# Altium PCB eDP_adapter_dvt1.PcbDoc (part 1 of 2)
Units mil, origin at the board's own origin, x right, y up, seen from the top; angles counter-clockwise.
Board outline 1964.57 x 1377.95 mil, 4 copper layers (Top Layer, Internal Plane 1, Internal Plane 2, Bottom Layer), stack 65.8 mil thick; 112 components, 78 nets, 1150 pads, 214 vias.
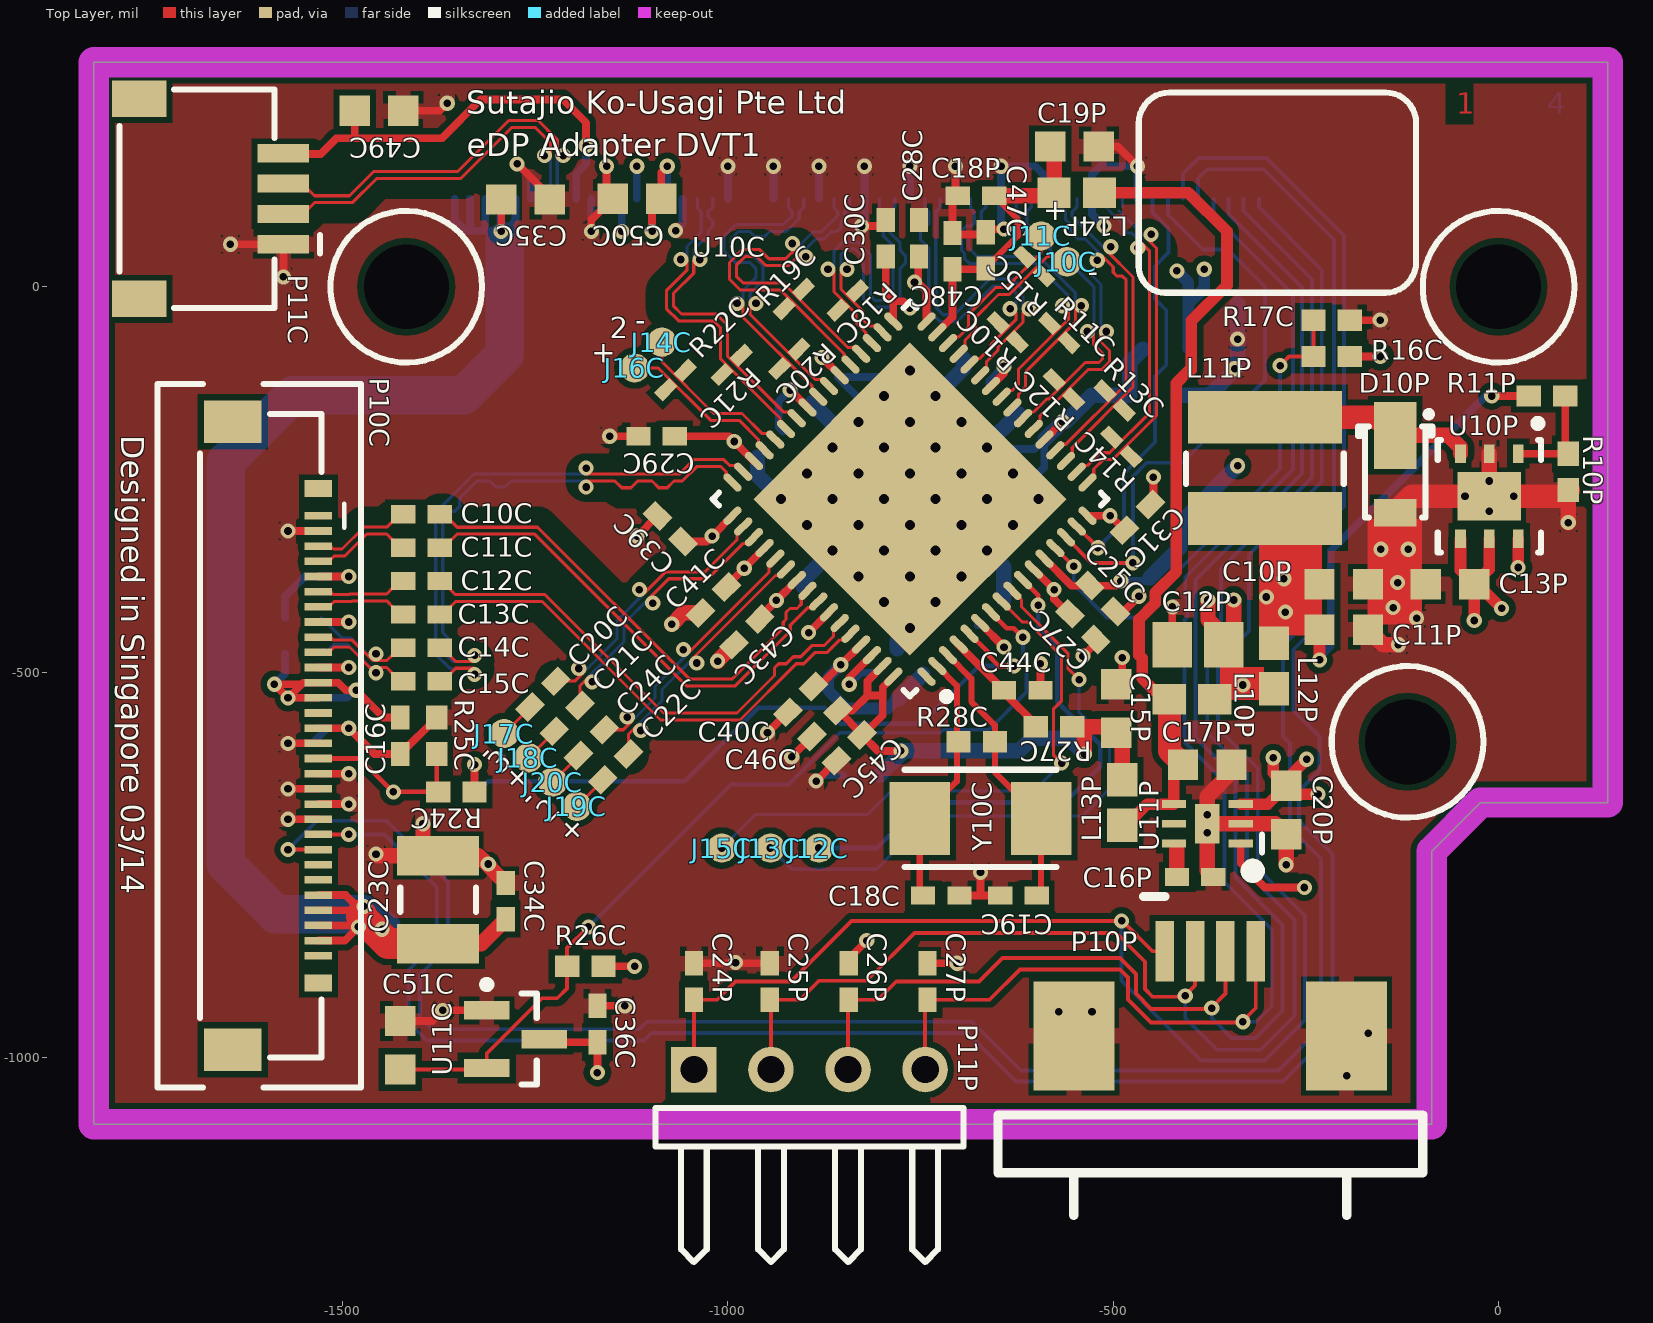
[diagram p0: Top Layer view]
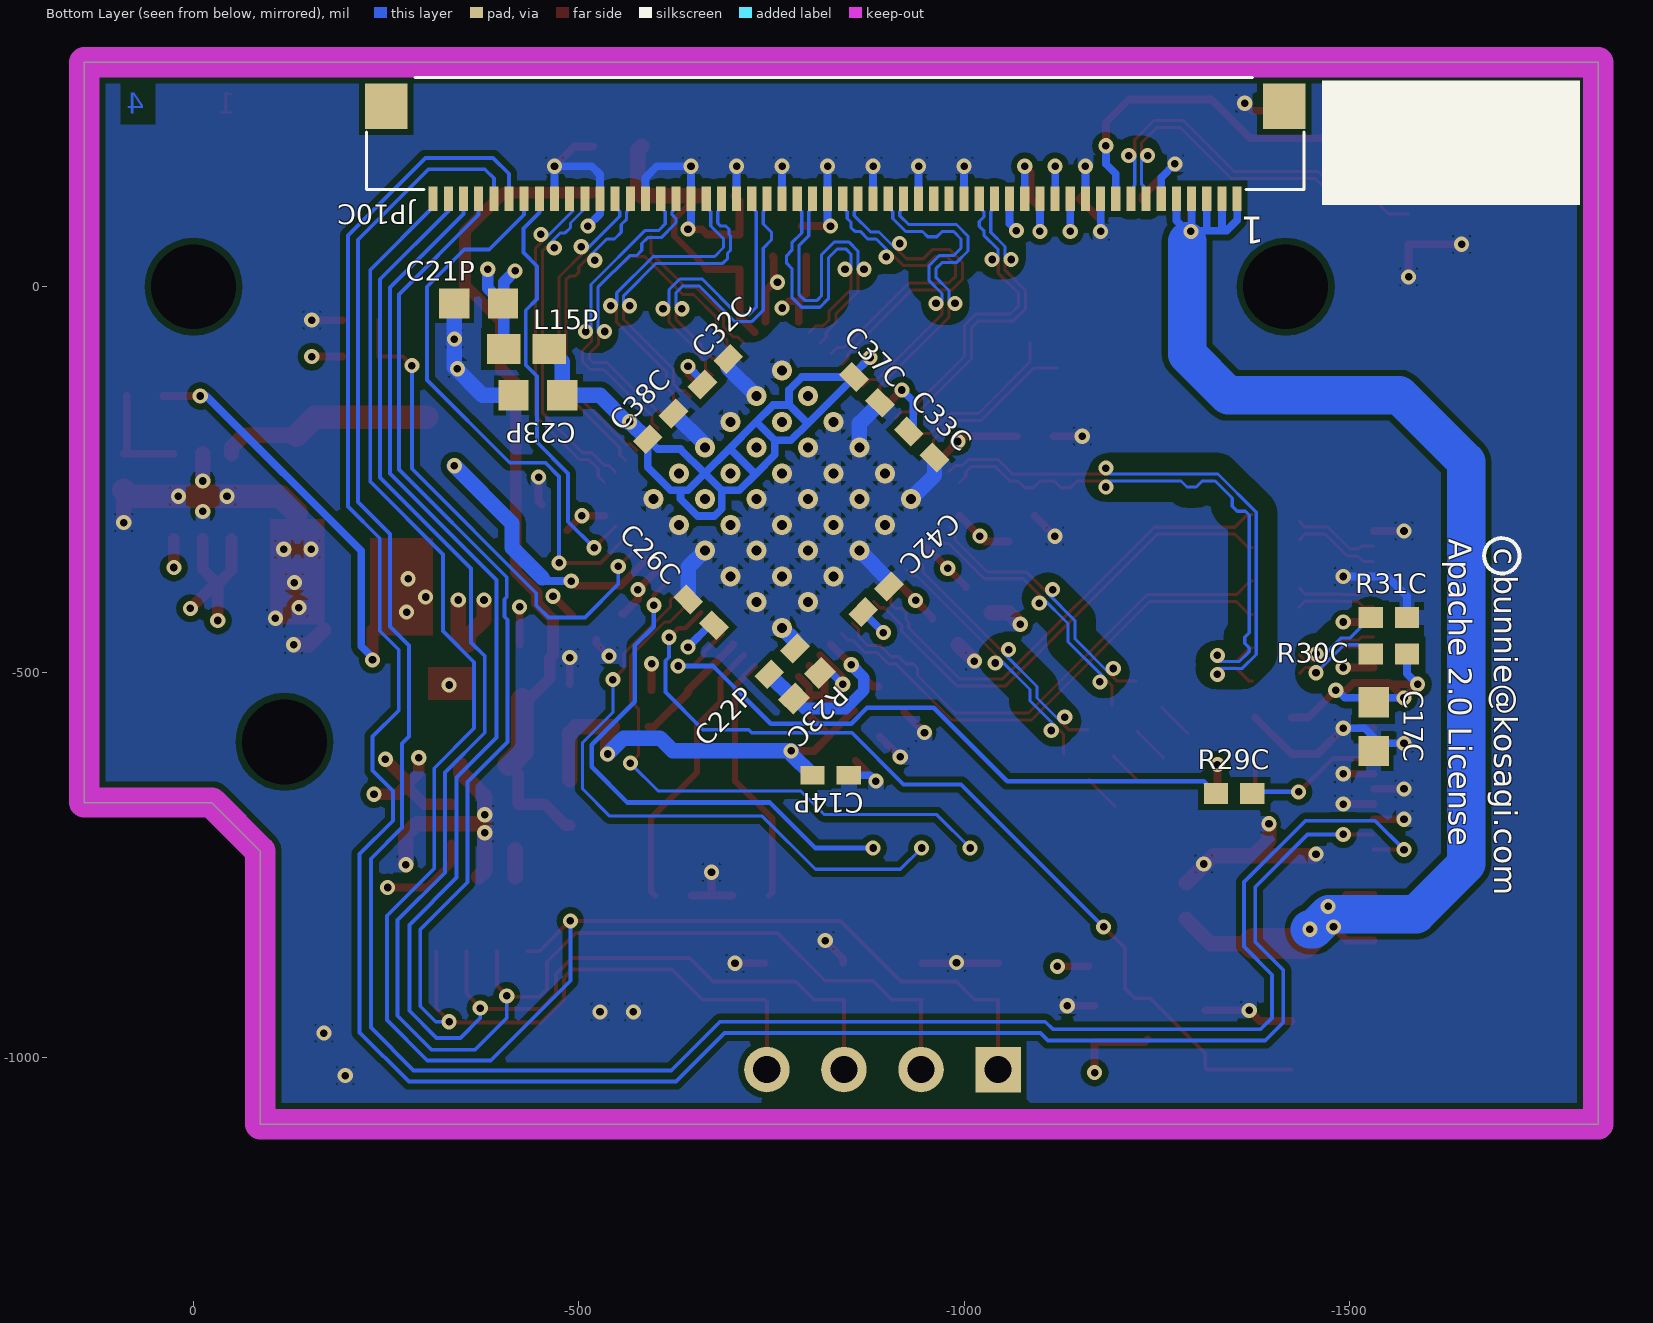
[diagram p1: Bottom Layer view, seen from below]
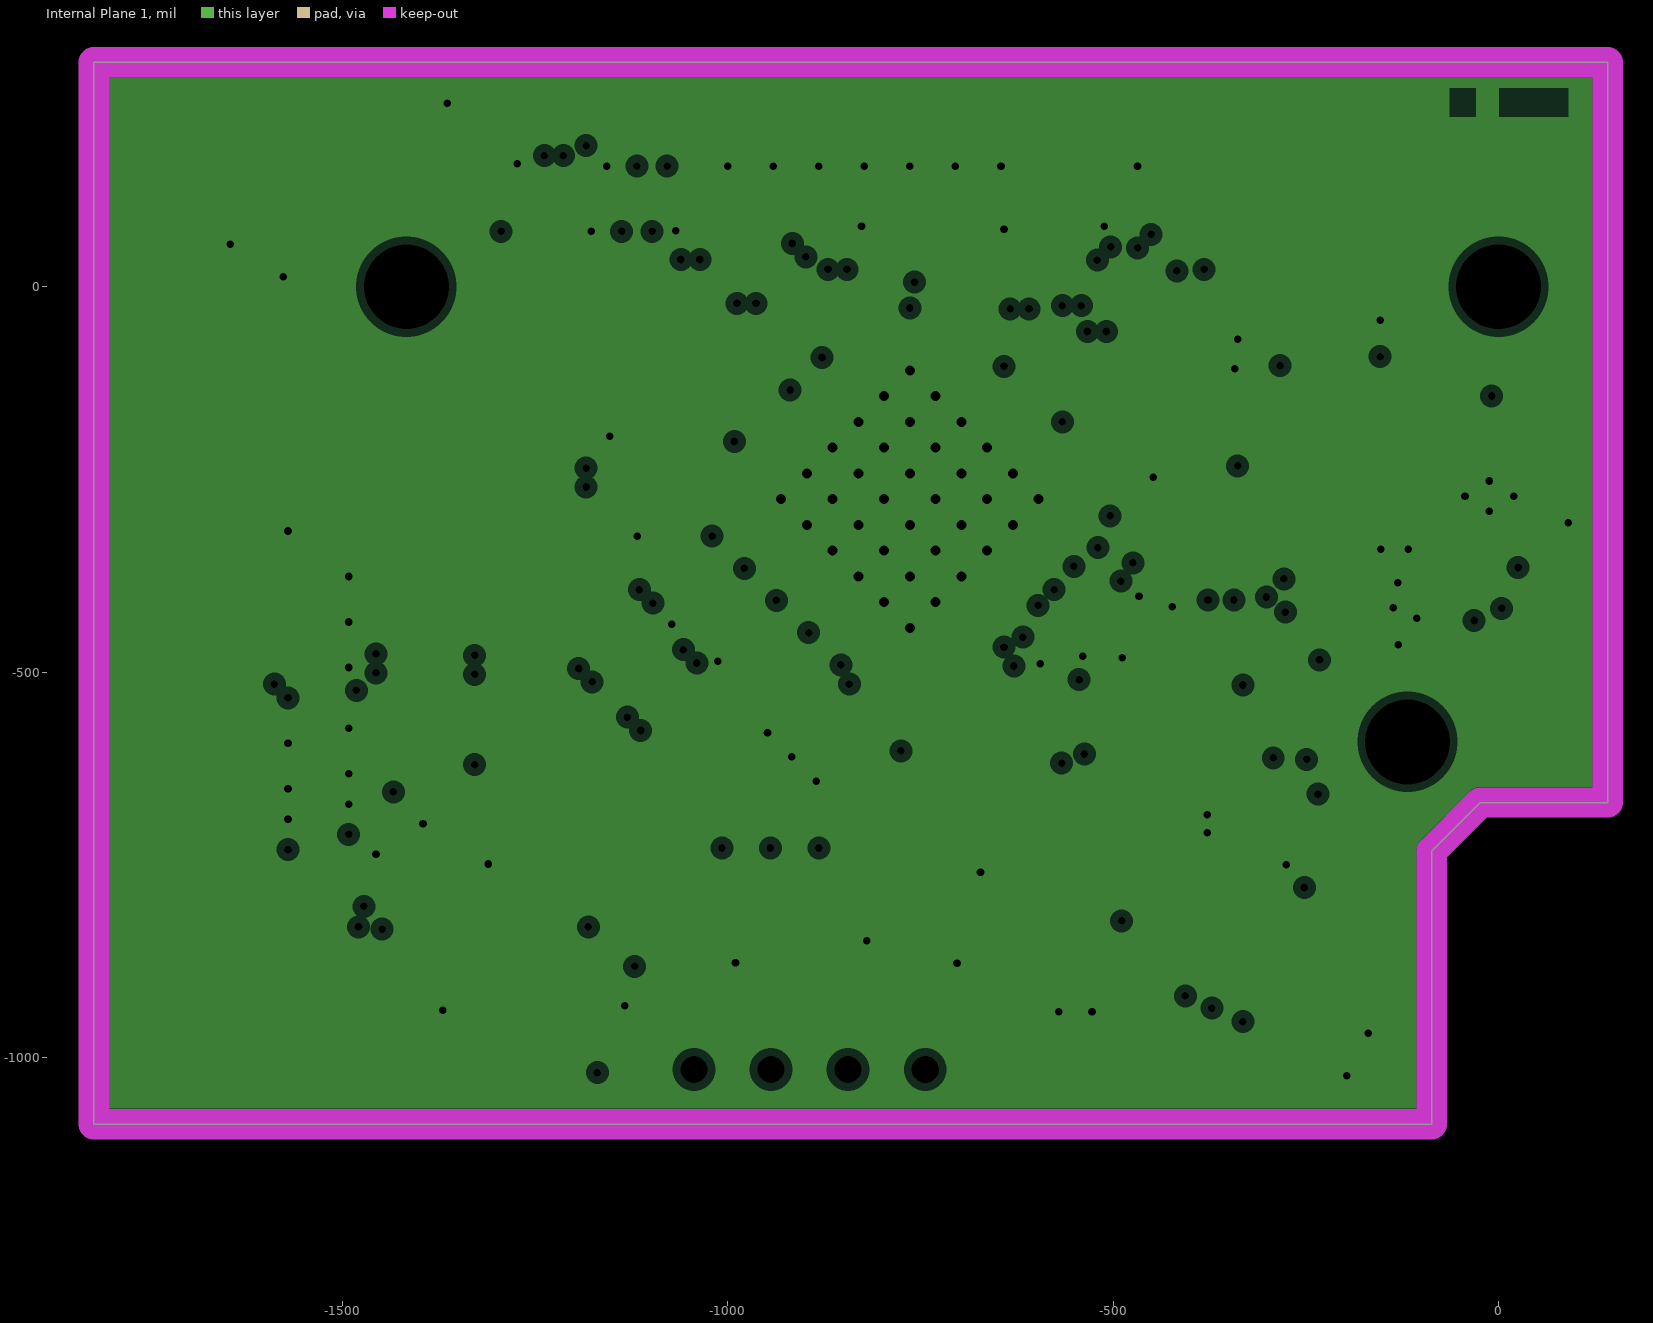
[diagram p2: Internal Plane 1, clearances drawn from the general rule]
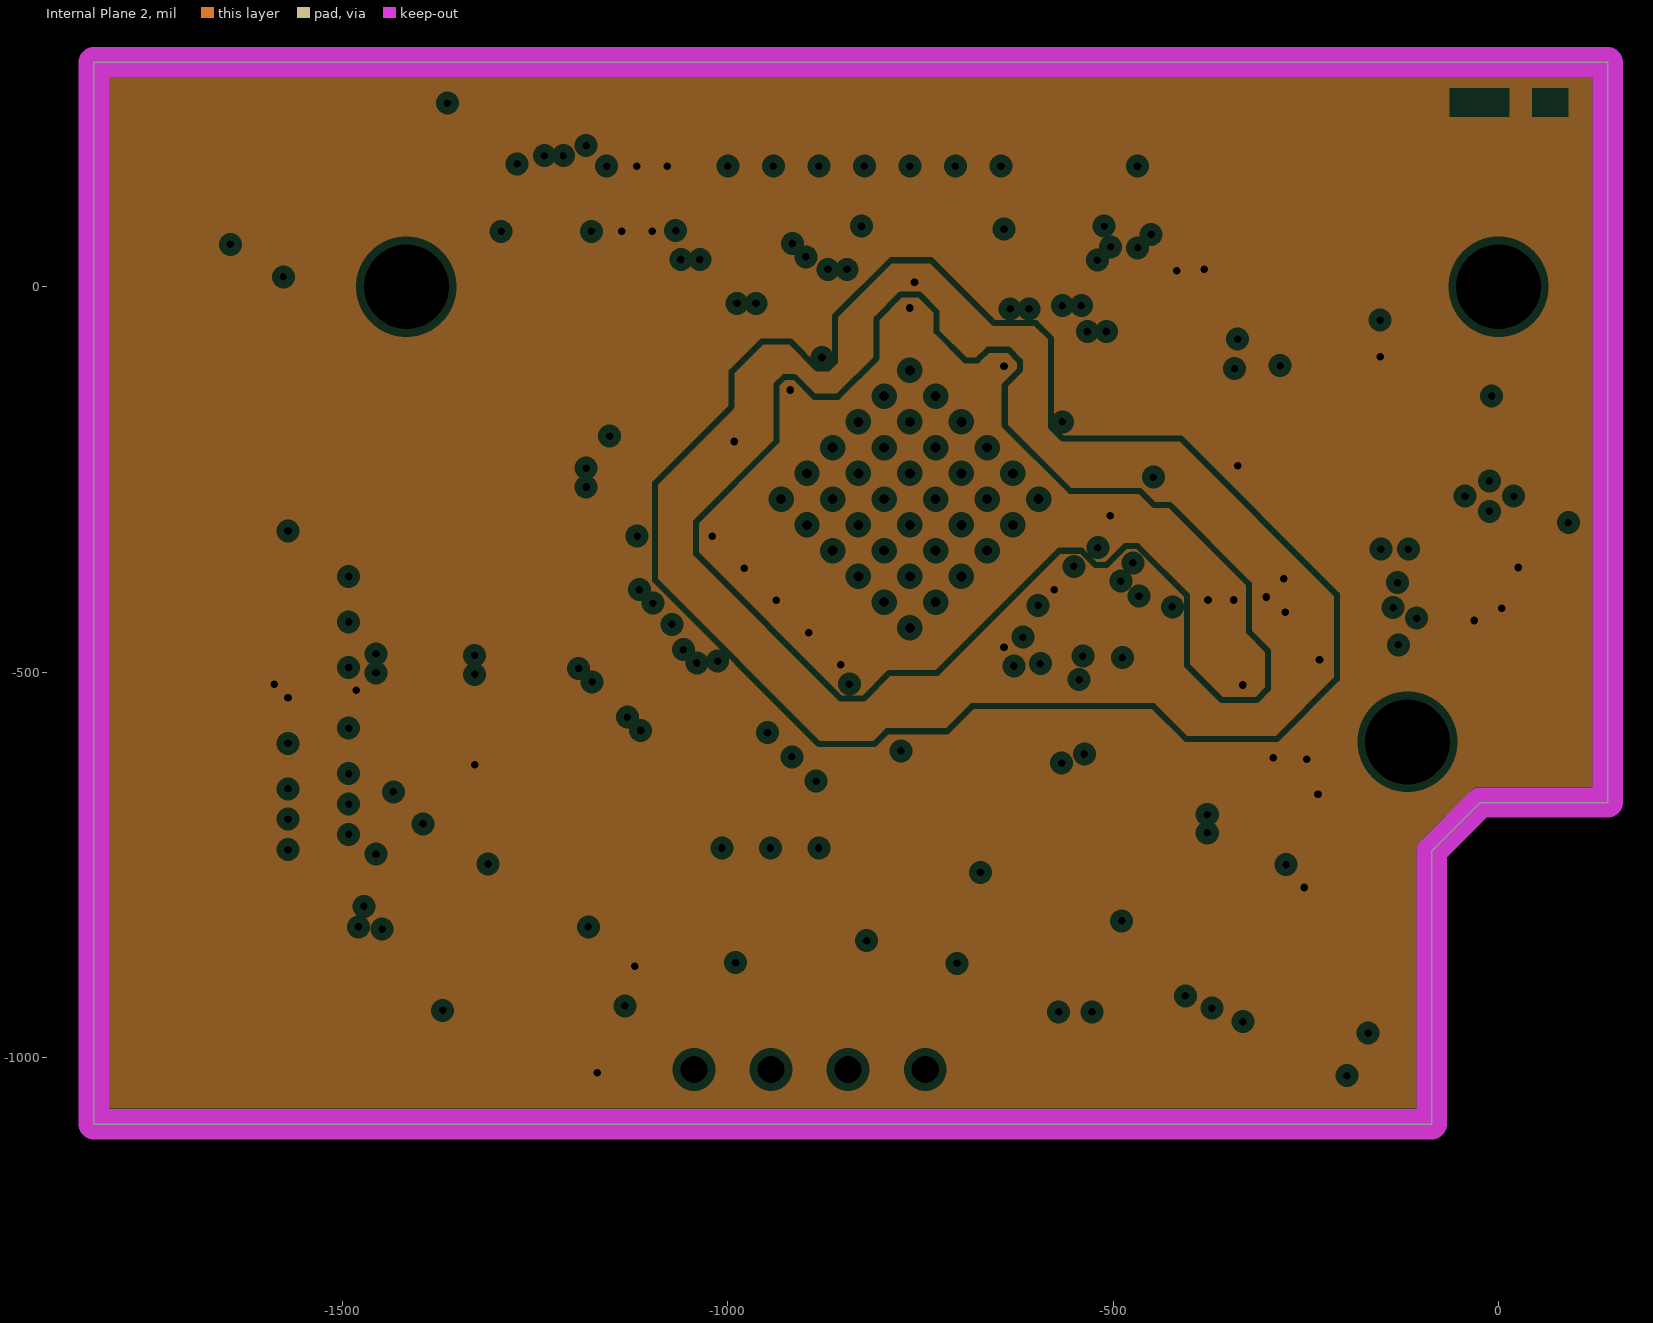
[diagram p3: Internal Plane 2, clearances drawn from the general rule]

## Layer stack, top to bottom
Top Solder: solder mask 0.4, Solder Resist, Dk 3.5
Top Layer: signal copper 1.4
Dielectric1: core 12.6, FR-4, Dk 4.8
Internal Plane 1: plane copper 1.4, net GND
Dielectric2: prepreg 35, FR-4, Dk 4.8
Internal Plane 2: plane copper 1.4, net (Multiple Nets)
Dielectric3: core 12.6, FR-4, Dk 4.8
Bottom Layer: signal copper 1.4
Bottom Solder: solder mask 0.4, Solder Resist, Dk 3.5

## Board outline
-1822.83,-1086.61 -86.61,-1086.61 -86.61,-732.28 -23.62,-669.29 141.73,-669.29 141.73,291.34 -1822.83,291.34

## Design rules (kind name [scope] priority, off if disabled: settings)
Clearance Clearance_diff_to_plane [InPoly vs IsTrack and InDifferentialPairClass('All Differential Pairs')] p1: gap=25
Clearance Clearance_poly [InPoly] p2: gap=8
Clearance Clearance_NPTH [PadIsPlated = 'False'] p3: gap=12
Clearance [All] p4: gap=4
ComponentClearance [All] p1 off: gap=10 collisioncheckmode=3 verticalgap=10 showdistances=FALSE
DiffPairsRouting [All] p1: maxlimit=10 minlimit=5 mostfreqgap=5 toplayer_minwidth=4.02 toplayer_maxwidth=4.02 toplayer_prefwidth=4.02 bottomlayer_minwidth=4.02 bottomlayer_maxwidth=4.02 bottomlayer_prefwidth=4.02 maxuncoupledlength=500
Height [All] p1 off: minheight=0 maxheight=1000 prefheight=500
HoleSize [All] p1: absolutevalues=TRUE maxlimit=175 minlimit=1 maxpercent=80.000 minpercent=20.000
MinimumSolderMaskSliver [All] p1 off: minsoldermaskwidth=10
NetAntennae [All] p1 off: netantennaetolerance=0
PlaneClearance [All] p1: clearance=10
PlaneConnect [All] p1: planeconnectstyle=Direct reliefexpansion=20 reliefentries=4 reliefconductorwidth=10 reliefairgap=10
PolygonConnect [All] p1: connectstyle=Relief reliefconductorwidth=20 reliefentries=4 polygonreliefangle="90 Angle" airgapwidth=6
RoomDefinition it6251_core [InComponentClass('it6251_core')] p1 off: confinementstyle=ConfineIn formatcopy=TRUE lockcomponents=FALSE outline 186.01,-958.67 397.64,-958.67 397.64,383.85 186.01,383.85
RoomDefinition power [InComponentClass('power')] p2 off: confinementstyle=ConfineIn formatcopy=TRUE lockcomponents=FALSE outline 12.78,1131.89 103.35,1131.89 103.35,998.03 12.78,998.03
RoutingVias [All] p1: holewidth=10 width=20 viastyle="Through Hole" minholewidth=8 minwidth=18 maxholewidth=15 maxwidth=30
SilkToSilkClearance [All] p1 off: silktosilkclearance=10
SilkToSolderMaskClearance SilkscreenOverComponentPads [IsPad] p1 off: minsilkscreentomaskgap=10 clearancetoexposedcopper=TRUE
SolderMaskExpansion [All] p1: expansion=2.76
Width [All] p1: maxlimit=200 minlimit=4 preferedwidth=8 minimp=50.000000 maximp=50.000000 favimp=50.000000
19 further rules are at their usual default settings.

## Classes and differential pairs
component class it6251_core: C10C C11C C12C C13C C14C C15C C16C C17C C18C C19C C20C C21C C22C C22P C23C C24C C25C C26C C27C C28C C29C C30C C31C C32C C33C C34C C35C C36C C37C C38C C39C C40C C41C C42C C43C C44C C45C C46C C47C C48C C49C C50C C51C J10C J11C J12C J13C J14C J15C J16C J17C J18C J19C J20C JP10C P10C P11C R10C R11C R12C R13C R14C R15C R16C R17C R18C R19C R20C R21C R22C R23C R24C R25C R26C R27C R28C R29C R30C R31C U10C U11C Y10C
component class power: C10P C11P C12P C13P C14P C15P C16P C17P C18P C19P C20P C21P C23P C24P C25P C26P C27P D10P L10P L11P L12P L13P L14P L15P P10P P11P R10P R11P U10P U11P
differential pair LVDS0_CLK: +LVDS0_CLK_P -LVDS0_CLK_N
differential pair LVDS0_TX_0: +LVDS0_TX_0_P -LVDS0_TX_0_N
differential pair LVDS0_TX_1: +LVDS0_TX_1_P -LVDS0_TX_1_N
differential pair LVDS0_TX_2: +LVDS0_TX_2_P -LVDS0_TX_2_N
differential pair LVDS0_TX_3: +LVDS0_TX_3_P -LVDS0_TX_3_N
differential pair LVDS1_CLK: +LVDS1_CLK_P -LVDS1_CLK_N
differential pair LVDS1_TX0: +LVDS1_TX0_P -LVDS1_TX0_N
differential pair LVDS1_TX1: +LVDS1_TX1_P -LVDS1_TX1_N
differential pair LVDS1_TX2: +LVDS1_TX2_P -LVDS1_TX2_N
differential pair LVDS1_TX_3: +LVDS1_TX_3_P -LVDS1_TX_3_N
differential pair USB_VID: +USB_VID_P -USB_VID_N
differential pair C_EDP_TX0: +C_EDP_TX0_P -C_EDP_TX0_N
differential pair C_EDP_TX1: +C_EDP_TX1_P -C_EDP_TX1_N
differential pair C_EDP_TXAUX: +C_EDP_TXAUX_P -C_EDP_TXAUX_N
differential pair EDP_TX0: +EDP_TX0_P -EDP_TX0_N
differential pair EDP_TX1: +EDP_TX1_P -EDP_TX1_N
differential pair EDP_TXAUX: +EDP_TXAUX_P -EDP_TXAUX_N
differential pair TX2: +TX2_P -TX2_N
differential pair TX3: +TX3_P -TX3_N

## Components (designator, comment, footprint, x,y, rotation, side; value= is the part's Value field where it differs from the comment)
C10C "0.1uF, 25V, X5R" CAPC1005N -1397.64,-295.28 r0 top
C10P "10uF, 10V, X5R, 20%" CAPC1608N -200.79,-385.83 r180 top
C11C "0.1uF, 25V, X5R" CAPC1005N -1397.64,-338.58 r0 top
C11P "10uF, 10V, X5R, 20%" CAPC1608N -200.79,-444.88 r180 top
C12C "0.1uF, 25V, X5R" CAPC1005N -1397.64,-381.89 r0 top
C12P "22uF, 10V, X5R, 20%" CAPC2012N -389.76,-464.57 r180 top
C13C "0.1uF, 25V, X5R" CAPC1005N -1397.64,-425.2 r0 top
C13P "4.7uF, 10V, X5R, 10%" CAPC1608N -62.99,-385.83 r180 top
C14C "0.1uF, 25V, X5R" CAPC1005N -1397.64,-468.5 r0 top
C14P "0.1uF, 25V, X5R" CAPC1005N -826.77,-633.86 r0 bottom
C15C "0.1uF, 25V, X5R" CAPC1005N -1397.64,-511.81 r0 top
C15P "10uF, 10V, X5R, 20%" CAPC1608N -496.06,-547.24 r270 top
C16C "0.1uF, 25V, X5R" CAPC1005N -1425.2,-582.68 r270 top
C16P "0.1uF, 25V, X5R" CAPC1005N -393.7,-765.75 r180 top
C17C "10uF, 10V, X5R, 20%" CAPC1608N -1531.5,-570.87 r90 bottom
C17P "10uF, 10V, X5R, 20%" CAPC1608N -377.95,-620.08 r180 top
C18C "22pF, NP0" CAPC1005N -723.14,-790.07 r180 top
C18P "0.1uF, 25V, X5R" CAPC1005N -678.15,118.11 r0 top
C19C "22pF, NP0" CAPC1005N -622.92,-790.07 r0 top
C19P "10uF, 10V, X5R, 20%" CAPC1608N -550.2,182.09 r180 top
C20C "0.1uF, 25V, X5R" CAPC1005N -1240.16,-528.54 r225 top
C20P "10uF, 10V, X5R, 20%" CAPC1608N -275.59,-679.13 r90 top
C21C "0.1uF, 25V, X5R" CAPC1005N -1208.66,-560.04 r225 top
C21P "10uF, 10V, X5R, 20%" CAPC1608N -370.08,-21.65 r180 bottom
C22C "0.1uF, 25V, X5R" CAPC1005N -1145.67,-623.03 r45 top
C22P "0.1uF, 25V, X5R" CAPC1005N -763.78,-486.22 r315 bottom
C23C "22uF, 25V, X5R, 10%" CAPC3225N -1375.98,-795.28 r90 top
C23P "10uF, 10V, X5R, 20%" CAPC1608N -446.85,-140.75 r180 bottom
C24C "0.1uF, 25V, X5R" CAPC1005N -1177.17,-591.54 r45 top
C24P "10nF, 25V, X5R" CAPC1005N -1044.09,-901.57 r270 top
C25C "0.1uF, 25V, X5R" CAPC1005N -513.78,-404.53 r315 top
C25P "10nF, 25V, X5R" CAPC1005N -945.67,-901.57 r270 top
C26C "0.1uF, 25V, X5R" CAPC1005N -658.69,-422.44 r45 bottom
C26P "10nF, 25V, X5R" CAPC1005N -843.31,-901.57 r270 top
C27C "0.1uF, 25V, X5R" CAPC1005N -539.37,-440.94 r315 top
C27P "10nF, 25V, X5R" CAPC1005N -740.94,-901.57 r270 top
C28C "0.1uF, 25V, X5R" CAPC1005N -751.97,62.99 r90 top
C29C "0.1uF, 25V, X5R" CAPC1005N -1092.52,-193.9 r180 top
C30C "0.1uF, 25V, X5R" CAPC1005N -795.28,62.99 r90 top
C31C "0.1uF, 25V, X5R" CAPC1005N -468.5,-299.21 r45 top
C32C "0.1uF, 25V, X5R" CAPC1005N -677.17,-110.24 r135 bottom
C33C "0.1uF, 25V, X5R" CAPC1005N -944.88,-204.72 r225 bottom
C34C "0.1uF, 25V, X5R" CAPC1005N -1288.39,-797.24 r90 top
C35C "1.0uF, 25V, 20% X5R" CAPC1608N -1262.8,113.19 r0 top
C36C "0.1uF, 25V, X5R" CAPC1005N -1169.29,-956.69 r90 top
C37C "0.1uF, 25V, X5R" CAPC1005N -874.02,-133.86 r225 bottom
C38C "0.1uF, 25V, X5R" CAPC1005N -606.3,-181.1 r135 bottom
C39C "0.1uF, 25V, X5R" CAPC1005N -1074.8,-313.98 r135 top
C40C "0.1uF, 25V, X5R" CAPC1005N -905.51,-535.43 r225 top
C41C "0.1uF, 25V, X5R" CAPC1005N -1018.7,-406.5 r225 top
C42C "0.1uF, 25V, X5R" CAPC1005N -885.83,-405.51 r135 bottom
C43C "0.1uF, 25V, X5R" CAPC1005N -975.39,-447.83 r225 top
C44C "0.1uF, 25V, X5R" CAPC1005N -618.11,-523.62 r0 top
C45C "0.1uF, 25V, X5R" CAPC1005N -842.52,-598.43 r225 top
C46C "1nF, 25V, X5R" CAPC1005N -874.02,-566.93 r225 top
C47C "0.1uF, 25V, X5R" CAPC1005N -665.35,47.24 r90 top
C48C "1nF, 25V, X5R" CAPC1005N -708.66,46.26 r90 top
C49C "10uF, 10V, X5R, 20%" CAPC1608N -1452.76,228.35 r180 top
C50C "10uF, 10V, X5R, 20%" CAPC1608N -1118.11,114.17 r0 top
C51C "DNP" CAPC1608N -1425.2,-984.25 r90 top
D10P "DFLS160-7" POWERDI-123 -133.86,-240.16 r270 top
J10C "test point (DNP)" TP_SMT_38mil -560.04,32.48 r90 top
J11C "test point (DNP)" TP_SMT_38mil -593.5,65.94 r90 top
J12C "test point (DNP)" TP_SMT_38mil -881.89,-728.35 r90 top
J13C "test point (DNP)" TP_SMT_38mil -944.88,-728.35 r135 top
J14C "test point (DNP)" TP_SMT_38mil -1085.63,-71.85 r135 top
J15C "test point (DNP)" TP_SMT_38mil -1007.87,-728.35 r135 top
J16C "test point (DNP)" TP_SMT_38mil -1121.06,-105.32 r135 top
J17C "test point (DNP)" TP_SMT_38mil -1290.35,-579.72 r90 top
J18C "test point (DNP)" TP_SMT_38mil -1258.86,-611.22 r90 top
J19C "test point (DNP)" TP_SMT_38mil -1195.87,-674.21 r90 top
J20C "test point (DNP)" TP_SMT_38mil -1227.36,-642.72 r90 top
JP10C "54-pin FFC MOLEX 51296-5494 or equiv" MOLEX_51296_5494 -1354.33,114.17 r0 bottom
L10P "BLM18KG121 (DNP)" INDC1608AN -397.64,-535.43 r180 top
L11P "2.2uH, coilcraft MSS5131-222ML" COILCRAFT_MSS5121 -303.15,-169.29 r0 top
L12P "BLM18KG121" INDC1608AN -291.34,-492.13 r270 top
L13P "BLM18KG121" INDC1608AN -488.19,-669.29 r90 top
L14P "BLM18KG121" INDC1608AN -547.24,122.05 r180 top
L15P "BLM18KG121" INDC1608AN -432.09,-80.71 r180 bottom
P10C "IPEX 20455-030E-*2 or Tyco (5-)2069716-2 or equiv" TYCO_5-2069716-2 -1531.5,-582.68 r270 top
P10P "AMP 487951-4" AMP_487951_4 -433.07,-862.2 r0 top
P11C "JST 04FMN-SMT-A-TF 1mm side-entry" JST_04FMN_SMT_A_TF -1576.77,55.12 r90 top
P11P "Male 2.54mm 4x1 right-angle header (DNP)" HDR1X4H -1044.09,-1015.75 r0 top
R10C "100, 1% (DNP)" RESC0603N -636.81,-59.06 r315 top
R10P "10k, 1%" RESC1005N 90.55,-240.16 r270 top
R11C "100, 1% (DNP)" RESC0603N -569.88,-60.04 r315 top
R11P "20k, 1%" RESC1005N 62.99,-141.73 r0 top
R12C "100, 1% (DNP)" RESC0603N -563.98,-132.87 r315 top
R13C "100, 1% (DNP)" RESC0603N -498.03,-147.64 r315 top
R14C "100, 1% (DNP)" RESC0603N -489.17,-207.68 r315 top
R15C "100, 1% (DNP)" RESC0603N -602.36,26.57 r315 top
R16C "10k, 1% (DNP)" RESC1005N -216.54,-90.55 r180 top
R17C "10k, 1%" RESC1005N -216.54,-43.31 r0 top
R18C "100, 1% (DNP)" RESC0603N -844.49,-17.72 r225 top
R19C "100, 1% (DNP)" RESC0603N -914.37,-15.75 r225 top
R20C "100, 1% (DNP)" RESC0603N -920.28,-93.5 r225 top
R21C "100, 1% (DNP)" RESC0603N -995.08,-101.38 r225 top
R22C "100, 1% (DNP)" RESC0603N -1067.91,-121.06 r45 top
R23C "820, 1%" RESC1005N -796.26,-517.72 r315 bottom
R24C "100k, 1% (DNP)" RESC1005N -1352.36,-655.51 r180 top
R25C "100k, 1%" RESC1005N -1377.95,-582.68 r90 top
R26C "10k, 1%" RESC1005N -1185.04,-881.89 r180 top
R27C "0 ohm" RESC1005N -576.77,-570.87 r180 top
R28C "1M, 5%" RESC1005N -677.17,-590.55 r180 top
R29C "33, 1%" RESC1005N -1350.39,-657.48 r180 bottom
R30C "100k, 1%" RESC1005N -1551.18,-476.38 r180 bottom
R31C "100k, 1%" RESC1005N -1551.18,-429.13 r180 bottom
U10C "IT6251" QFN50P900X900-64WAN -763.78,-275.59 r135 top
U10P "LMR10510YSD" SON95P300X300X80-7V -11.97,-271.78 r270 top
U11C "APX803-29-SAG-7 2.93V setpoint" SOT23-3N -1275.59,-976.38 r0 top
U11P "MIC5319-1.8YML" MICREL_MLF2x2_6 -342.52,-722.44 r180 top
Y10C "27 MHz, 50ppm, 8-18pF, ESR <80 ohm" NDK_NX5032A -750.98,-689.85 r0 top

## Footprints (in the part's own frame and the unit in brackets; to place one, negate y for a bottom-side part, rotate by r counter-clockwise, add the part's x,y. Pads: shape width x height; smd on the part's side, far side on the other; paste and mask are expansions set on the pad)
AMP_487951_4 [mm] "4-pin FF connector, 1mm pitch"
  rect 0.61x2 smd: 1(0,0) 2(1,0) 3(2,0) 4(3,0)
  rect 2.68x3.6 smd: MP1(-2.99,-2.8) MP2(5.99,-2.8)
  silkscreen extent -5.5,-8.7 8.5,1.8, body extent -4.46,-5.85 7.46,0.7, height 2.7
CAPC1005N [mm] "Chip Capacitor, Body 1.0x0.5mm, IPC Medium Density"
  rect 0.8x0.6 smd: 1(-0.6,0) 2(0.6,0)
  body extent -0.55,-0.3 0.55,0.3, height 0.6
CAPC1608N [mm] "Chip Capacitor, Body 1.6x0.8mm, IPC Medium Density"
  rect 1x1 smd: 1(-0.8,0) 2(0.8,0)
  body extent -0.87,-0.48 0.87,0.48, height 0.85
CAPC2012N [mm] "Chip Capacitor, Body 2.0x1.3mm, IPC Medium Density"
  rect 1.3x1.5 smd: 1(-0.85,0) 2(0.85,0)
  body extent -1.1,-0.72 1.1,0.72, height 1.1
CAPC3225N [mm] "Chip Capacitor, Body 3.2x2.5mm, IPC Medium Density"
  rect 1.3x2.7 smd: 1(-1.45,0) 2(1.45,0)
  silkscreen extent -0.4,-1.25 0.4,1.25, body extent -1.7,-1.35 1.7,1.35, height 1.35
COILCRAFT_MSS5121 [mm] "Coilcraft shielded power inductor"
  rect 5.08x1.74 smd mask+0.075: 1(0,0) 2(0,-3.34)
  silkscreen extent -2.6,-2.2 2.6,-1.2, body extent -2.6,-4.3 2.6,0.9, height 2.2
HDR1X4H [mm] "Connector; Header; 4 Position; Right Angle"
  rect 1.5x1.5 hole 0.9: 1(0,0)
  round 1.5 hole 0.9: 2(2.54,0) 3(5.08,0) 4(7.62,0)
  silkscreen extent -1.27,-6.35 8.89,-1.27
INDC1608AN [mm] "Chip Inductor, Body 1.6x0.8mm, IPC Medium Density"
  rect 1.1x1 smd: 1(-0.75,0) 2(0.75,0)
  body extent -0.9,-0.5 0.9,0.5, height 1
JST_04FMN_SMT_A_TF [mm] "JST 4-pin side-entry 1mm SMT FFC/FPC connector"
  rect 1.2x1.8 smd mask+0.07: 0(-1.8,4.75) 0(4.8,4.75)
  rect 0.6x1.7 smd mask+0.07: 1(0,0) 2(1,0) 3(2,0) 4(3,0)
  silkscreen extent -2.1,-1.2 5.1,5.4, body extent -2.1,0.3 5.1,5.4, height 3.05
MICREL_MLF2x2_6 [mm] "6-pin 2x2mm MLF package (Micrel)"
  rect 0.8x0.26 smd mask+0.07: 1(-0.2,0) 2(-0.2,-0.65) 3(-0.2,-1.3) 4(2,-1.3) 5(2,-0.65) 6(2,0)
  rect 0.8x1.3 smd mask+0.07: PAD(0.9,-0.65)
  silkscreen extent -0.9,-0.3 -0.4,1.1, body extent -0.1,-1.7 1.9,0.3, height 0.85
MOLEX_51296_5494 [mm] "54-pin FF connector"
  rect 1.4x1.5 smd mask+0.07: 0(-1.55,-3.05) 0(28.05,-3.05)
  rect 0.3x0.8 smd mask+0.07: 1(0,0) 2(0.5,0) 3(1,0) 4(1.5,0) 5(2,0) 6(2.5,0) 7(3,0) 8(3.5,0) 9(4,0) 10(4.5,0) 11(5,0) 12(5.5,0) 13(6,0) 14(6.5,0) 15(7,0) 16(7.5,0) 17(8,0) 18(8.5,0) 19(9,0) 20(9.5,0) 21(10,0) 22(10.5,0) 23(11,0) 24(11.5,0) 25(12,0) 26(12.5,0) 27(13,0) 28(13.5,0) 29(14,0) 30(14.5,0) 31(15,0) 32(15.5,0) 33(16,0) 34(16.5,0) 35(17,0) 36(17.5,0) 37(18,0) 38(18.5,0) 39(19,0) 40(19.5,0) 41(20,0) 42(20.5,0) 43(21,0) 44(21.5,0) 45(22,0) 46(22.5,0) 47(23,0) 48(23.5,0) 49(24,0) 50(24.5,0) 51(25,0) 52(25.5,0) 53(26,0) 54(26.5,0)
  silkscreen extent -2.2,-4 28.7,-0.3, body extent -2.2,-4 28.7,-0.3, height 1.3
NDK_NX5032A [mm] "5x3.2mm crystal, SMT"
  rect 2x2.4 smd: 1(0,0) 2(4,0)
  silkscreen extent -0.5,-1.6 4.5,1.6
POWERDI-123 [mm] "SOD-123 power package, Diodes Inc"
  rect 0.9x1.4 smd: 1(1.35,0)
  rect 2.2x1.4 smd: 2(-1.2,0)
  silkscreen extent -1.95,-1.22 1.5,1.23, body extent -1.5,-0.96 1.5,0.96, height 1
QFN50P900X900-64WAN [mm] "QFN, 64-Leads, Body 9x9mm, Pitch 0.5mm, IPC Medium Density"
  oval 0.75x0.25 smd: 1(-4.525,3.75) 2(-4.525,3.25) 3(-4.525,2.75) 4(-4.525,2.25) 5(-4.525,1.75) 6(-4.525,1.25) 7(-4.525,0.75) 8(-4.525,0.25) 9(-4.525,-0.25) 10(-4.525,-0.75) 11(-4.525,-1.25) 12(-4.525,-1.75) 13(-4.525,-2.25) 14(-4.525,-2.75) 15(-4.525,-3.25) 16(-4.525,-3.75) 33(4.525,-3.75) 34(4.525,-3.25) 35(4.525,-2.75) 36(4.525,-2.25) 37(4.525,-1.75) 38(4.525,-1.25) 39(4.525,-0.75) 40(4.525,-0.25) 41(4.525,0.25) 42(4.525,0.75) 43(4.525,1.25) 44(4.525,1.75) 45(4.525,2.25) 46(4.525,2.75) 47(4.525,3.25) 48(4.525,3.75)
  oval 0.25x0.75 smd: 17(-3.75,-4.525) 18(-3.25,-4.525) 19(-2.75,-4.525) 20(-2.25,-4.525) 21(-1.75,-4.525) 22(-1.25,-4.525) 23(-0.75,-4.525) 24(-0.25,-4.525) 25(0.25,-4.525) 26(0.75,-4.525) 27(1.25,-4.525) 28(1.75,-4.525) 29(2.25,-4.525) 30(2.75,-4.525) 31(3.25,-4.525) 32(3.75,-4.525) 49(3.75,4.525) 50(3.25,4.525) 51(2.75,4.525) 52(2.25,4.525) 53(1.75,4.525) 54(1.25,4.525) 55(0.75,4.525) 56(0.25,4.525) 57(-0.25,4.525) 58(-0.75,4.525) 59(-1.25,4.525) 60(-1.75,4.525) 61(-2.25,4.525) 62(-2.75,4.525) 63(-3.25,4.525) 64(-3.75,4.525)
  rect 7.3x7.3 smd mask-5: 65(0,0)
  silkscreen extent -5.57,-4.6 4.6,4.6, body extent -4.58,-4.58 4.58,4.58, height 0.8
RESC0603N [mm] "Chip Resistor, Body 0.6x0.3mm, IPC Medium Density"
  rect 0.7x0.4 smd: 1(-0.45,0) 2(0.45,0)
  body extent -0.32,-0.17 0.32,0.17, height 0.3
RESC1005N [mm] "Chip Resistor, Body 1.1x0.5mm, IPC Medium Density"
  rect 0.8x0.7 smd: 1(-0.6,0) 2(0.6,0)
  body extent -0.55,-0.3 0.55,0.3, height 0.4
SON95P300X300X80-7V [mm] "SON, 6-Leads, Body 3x3 mm, Pitch 0.95mm, NSC Recommended"
  rect 0.6x0.35 smd paste-0.175 mask+0.051: 1(-1.4,0.95) 2(-1.4,0) 3(-1.4,-0.95) 4(1.4,-0.95) 5(1.4,0) 6(1.4,0.95)
  rect 1.6x2.1 smd paste-0.8 mask+0.051: 7(0,0)
  silkscreen extent -2.52,-1.7 1.85,1.73, body extent -1.55,-1.55 1.55,1.55, height 0.8
SOT23-3N [mm] "SOT23, 3-Leads, Body 2.9x1.3mm, Pitch 0.95mm, Lead Span 2.5mm, IPC Medium Density"
  rect 1.5x0.6 smd: 1(-0.95,0.95) 2(-0.95,-0.95) 3(0.95,0)
  silkscreen extent -1.07,-1.5 0.7,1.92, body extent -0.7,-1.5 0.7,1.5, height 1.1
TP_SMT_38mil [mil] "38 mil round test point, SMT"
  round 38 smd: 1(0,0)
TYCO_5-2069716-2 [mm] "LCEDI 0.5mm connector / CABLINE-VS 30-pin connector"
  rect 1.4x1.9 smd mask+0.07: 0(-10.35,-2.82) 0(10.35,-2.82)
  rect 0.55x0.9 smd mask+0.07: 0(-8.15,0) 0(8.15,0)
  rect 0.25x0.9 smd mask+0.07: 1(-7.25,0) 2(-6.75,0) 3(-6.25,0) 4(-5.75,0) 5(-5.25,0) 6(-4.75,0) 7(-4.25,0) 8(-3.75,0) 9(-3.25,0) 10(-2.75,0) 11(-2.25,0) 12(-1.75,0) 13(-1.25,0) 14(-0.75,0) 15(-0.25,0) 16(0.25,0) 17(0.75,0) 18(1.25,0) 19(1.75,0) 20(2.25,0) 21(2.75,0) 22(3.25,0) 23(3.75,0) 24(4.25,0) 25(4.75,0) 26(5.25,0) 27(5.75,0) 28(6.25,0) 29(6.75,0) 30(7.25,0)
  silkscreen extent -11.6,-5.3 11.6,1.4, body extent -10.62,-3.95 10.63,0, height 0.97

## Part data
C10C C10P C11C C11P C12C C12P C13C C13P C14C C14P C15C C15P C16C C16P C17C C17P C18C C18P C19C C19P C20C C20P C21C C21P C22C C22P C23C C23P C24C C24P C25C C25P C26C C26P C27C C27P C28C C29C C30C C31C C32C C33C C34C C35C C36C C37C C38C C39C C40C C41C C42C C43C C44C C45C C46C C47C C48C C49C C50C C51C: library part "Cap Semi", "Capacitor (Semiconductor SIM Model)"
D10P: library part "D Schottky", "Schottky Diode"
J10C J11C J12C J13C J14C J15C J16C J17C J18C J19C J20C: library part CON1, "Connector"
JP10C: library part HEADER_54, "Flat flex connector, 54 positions"
L10P L11P L12P L13P L14P L15P: library part "Inductor Iron", "Magnetic-Core Inductor"
P10C: library part "Header 30"
P10P: library part TFT_TP_CON
P11C: library part "Header 4", "Header, 4-Pin"
P11P: library part "Header 4H", "Header, 4-Pin, Right Angle"
R10C R10P R11C R11P R12C R13C R14C R15C R16C R17C R18C R19C R20C R21C R22C R23C R24C R25C R26C R27C R28C R29C R30C R31C: library part Res1, "Resistor"
U10C: "LVDS to eDP converter"
U10P: library part LMR10515XSD, "NatSemi 1.5A step-down regulator in LLP"
U11C: library part RESET_SOT23, "Reset monitor. Voltage specified by XX in P/N. Multiple vendors."
U11P: library part MIC5319-XXYML, "500 mA uCap ultra-low dropout high PSRR LDO regulator"
Y10C: library part XTAL, "Crystal Oscillator"

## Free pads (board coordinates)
  round 47.24 hole 110.24 unplated: 0(-118.11,-590.55) 1(0,0) 2(-1417.32,0)
  rect 2x34 on Bottom Overlay: 1(-1778.25,-155.02) 1(-1736.25,-237.02) 1(-1736.25,-73.02) 1(-1542.25,-237.02) 1(-1542.25,-73.02)
  rect 2x38 on Bottom Overlay: 1(-1776.25,-155.02) 1(-1774.25,-155.02) 1(-1772.25,-155.02) 1(-1734.25,-237.02) 1(-1734.25,-73.02)
  rect 2x40 on Bottom Overlay: 1(-1770.25,-156.02) 1(-1544.25,-236.02) 1(-1544.25,-74.02)
  rect 2x42 on Bottom Overlay: 1(-1768.25,-155.02) 1(-1766.25,-155.02) 1(-1764.25,-155.02) 1(-1762.25,-155.02) 1(-1760.25,-155.02)
  rect 2x44 on Bottom Overlay: 1(-1758.25,-156.02) 1(-1732.25,-236.02) 1(-1732.25,-74.02) 1(-1546.25,-236.02) 1(-1546.25,-74.02)
  rect 2x46 on Bottom Overlay: 1(-1756.25,-155.02) 1(-1754.25,-155.02) 1(-1752.25,-155.02) 1(-1750.25,-155.02)
  rect 2x4 on Bottom Overlay: 1(-1748.25,-240.02) 1(-1748.25,-70.02) 1(-1542.25,-198.02) 1(-1542.25,-112.02)
  rect 2x48 on Bottom Overlay: 1(-1748.25,-156.02) 1(-1730.25,-236.02) 1(-1730.25,-74.02)
  rect 2x10 on Bottom Overlay: 1(-1746.25,-239.02) 1(-1746.25,-71.02) 1(-1544.25,-199.02) 1(-1544.25,-111.02) 1(-1532.25,-239.02) 1(-1532.25,-71.02)
  rect 2x50 on Bottom Overlay: 1(-1746.25,-155.02) 1(-1744.25,-155.02) 1(-1742.25,-155.02) 1(-1740.25,-155.02)
  rect 2x14 on Bottom Overlay: 1(-1744.25,-239.02) 1(-1744.25,-71.02) 1(-1546.25,-201.02) 1(-1546.25,-109.02) 1(-1534.25,-239.02)
  rect 2x20 on Bottom Overlay: 1(-1742.25,-72.02) 1(-1536.25,-72.02) 1(-1536.25,-238.02)
  rect 2x18 on Bottom Overlay: 1(-1742.25,-239.02)
  rect 2x24 on Bottom Overlay: 1(-1740.25,-238.02) 1(-1740.25,-72.02) 1(-1538.25,-238.02)
  rect 2x28 on Bottom Overlay: 1(-1738.25,-238.02)
  rect 2x58 on Bottom Overlay: 1(-1738.25,-155.02)
  rect 2x30 on Bottom Overlay: 1(-1738.25,-73.02) 1(-1540.25,-237.02) 1(-1540.25,-73.02)
  rect 2x68 on Bottom Overlay: 1(-1736.25,-156.02) 1(-1586.25,-212.02) 1(-1586.25,-98.02) 1(-1584.25,-98.02) 1(-1584.25,-212.02) 1(-1582.25,-98.02) 1(-1580.25,-214.02) 1(-1580.25,-96.02) 1(-1576.25,-216.02) 1(-1576.25,-94.02) 1(-1548.25,-84.02)
  rect 2x78 on Bottom Overlay: 1(-1734.25,-155.02) 1(-1674.25,-97.02) 1(-1674.25,-213.02) 1(-1604.25,-215.02) 1(-1604.25,-95.02)
  rect 2x86 on Bottom Overlay: 1(-1732.25,-155.02)
  rect 2x98 on Bottom Overlay: 1(-1730.25,-155.02) 1(-1640.25,-245.02) 1(-1638.25,-245.02) 1(-1636.25,-245.02)
  rect 2x214 on Bottom Overlay: 1(-1728.25,-155.02) 1(-1718.25,-155.02)
  rect 2x218 on Bottom Overlay: 1(-1726.25,-155.02) 1(-1722.25,-155.02) 1(-1720.25,-155.02)
  rect 2x222 on Bottom Overlay: 1(-1724.25,-155.02)
  rect 2x210 on Bottom Overlay: 1(-1716.25,-155.02) 1(-1714.25,-155.02)
  rect 2x206 on Bottom Overlay: 1(-1712.25,-155.02)
  rect 2x202 on Bottom Overlay: 1(-1710.25,-155.02)
  rect 2x200 on Bottom Overlay: 1(-1708.25,-156.02)
  rect 2x198 on Bottom Overlay: 1(-1706.25,-155.02)
  rect 2x194 on Bottom Overlay: 1(-1704.25,-155.02)
  rect 2x192 on Bottom Overlay: 1(-1702.25,-156.02)
  rect 2x190 on Bottom Overlay: 1(-1700.25,-155.02) 1(-1682.25,-155.02) 1(-1680.25,-155.02)
  rect 2x186 on Bottom Overlay: 1(-1698.25,-155.02) 1(-1686.25,-155.02) 1(-1684.25,-155.02)
  rect 2x184 on Bottom Overlay: 1(-1696.25,-156.02)
  rect 2x182 on Bottom Overlay: 1(-1694.25,-155.02) 1(-1692.25,-155.02) 1(-1690.25,-155.02) 1(-1688.25,-155.02)
  rect 2x92 on Bottom Overlay: 1(-1678.25,-206.02) 1(-1618.25,-236.02) 1(-1618.25,-74.02)
  rect 2x90 on Bottom Overlay: 1(-1678.25,-105.02) 1(-1660.25,-235.02) 1(-1660.25,-77.02)
  rect 2x84 on Bottom Overlay: 1(-1676.25,-210.02) 1(-1676.25,-100.02) 1(-1616.25,-80.02) 1(-1616.25,-230.02)
  rect 2x76 on Bottom Overlay: 1(-1672.25,-216.02) 1(-1672.25,-94.02) 1(-1608.25,-92.02) 1(-1606.25,-216.02) 1(-1606.25,-94.02) 1(-1596.25,-212.02) 1(-1596.25,-98.02) 1(-1594.25,-212.02) 1(-1594.25,-98.02) 1(-1554.25,-228.02) 1(-1554.25,-82.02)
  rect 2x74 on Bottom Overlay: 1(-1670.25,-217.02) 1(-1670.25,-93.02) 1(-1668.25,-219.02) 1(-1614.25,-223.02) 1(-1614.25,-87.02) 1(-1608.25,-219.02) 1(-1592.25,-213.02) 1(-1592.25,-99.02) 1(-1564.25,-223.02) 1(-1560.25,-225.02) 1(-1560.25,-85.02) 1(-1558.25,-227.02) 1(-1558.25,-85.02) 1(-1556.25,-227.02) 1(-1556.25,-83.02)
  rect 2x72 on Bottom Overlay: 1(-1668.25,-92.02) 1(-1666.25,-90.02) 1(-1666.25,-220.02) 1(-1664.25,-222.02) 1(-1664.25,-88.02) 1(-1612.25,-222.02) 1(-1612.25,-90.02) 1(-1610.25,-220.02) 1(-1610.25,-90.02) 1(-1590.25,-212.02) 1(-1590.25,-98.02) 1(-1588.25,-212.02) 1(-1588.25,-98.02) 1(-1568.25,-90.02) 1(-1566.25,-222.02) 1(-1566.25,-88.02) 1(-1564.25,-88.02) 1(-1562.25,-224.02) 1(-1562.25,-86.02) 1(-1552.25,-228.02) 1(-1552.25,-82.02)
  rect 2x80 on Bottom Overlay: 1(-1662.25,-228.02) 1(-1662.25,-82.02) 1(-1602.25,-214.02) 1(-1602.25,-98.02) 1(-1600.25,-212.02) 1(-1600.25,-98.02) 1(-1598.25,-212.02) 1(-1598.25,-98.02)
  rect 2x100 on Bottom Overlay: 1(-1658.25,-240.02) 1(-1658.25,-70.02) 1(-1650.25,-244.02) 1(-1650.25,-66.02) 1(-1648.25,-244.02) 1(-1648.25,-66.02) 1(-1646.25,-66.02) 1(-1646.25,-244.02) 1(-1644.25,-244.02) 1(-1644.25,-66.02) 1(-1642.25,-244.02) 1(-1642.25,-66.02) 1(-1640.25,-66.02) 1(-1638.25,-66.02) 1(-1636.25,-66.02) 1(-1634.25,-244.02) 1(-1634.25,-66.02) 1(-1632.25,-244.02) 1(-1632.25,-66.02) 1(-1630.25,-244.02) 1(-1630.25,-66.02) 1(-1628.25,-244.02) 1(-1628.25,-66.02) 1(-1626.25,-244.02)
  rect 2x102 on Bottom Overlay: 1(-1656.25,-243.02) 1(-1654.25,-243.02) 1(-1654.25,-67.02) 1(-1652.25,-243.02) 1(-1652.25,-67.02) 1(-1626.25,-67.02) 1(-1624.25,-243.02) 1(-1624.25,-67.02) 1(-1622.25,-243.02) 1(-1622.25,-67.02) 1(-1620.25,-241.02) 1(-1620.25,-69.02)
  rect 2x104 on Bottom Overlay: 1(-1656.25,-68.02)
  rect 2x66 on Bottom Overlay: 1(-1582.25,-213.02) 1(-1548.25,-227.02)
  rect 2x70 on Bottom Overlay: 1(-1578.25,-215.02) 1(-1578.25,-95.02) 1(-1574.25,-217.02) 1(-1574.25,-93.02) 1(-1572.25,-219.02) 1(-1572.25,-91.02) 1(-1570.25,-219.02) 1(-1570.25,-91.02) 1(-1568.25,-221.02) 1(-1550.25,-227.02) 1(-1550.25,-83.02)
  rect 2x26 on Bottom Overlay: 1(-1538.25,-73.02)
  rect 2x16 on Bottom Overlay: 1(-1534.25,-72.02)
  rect 2x6 on Bottom Overlay: 1(-1530.25,-239.02) 1(-1530.25,-71.02)
  rect 8x2 on Top Overlay: 1(-440.83,51.21) 1(-402.83,115.21) 1(-400.83,209.21) 1(-396.83,215.21) 1(-384.83,183.21) 1(-378.83,11.21) 1(-352.83,171.21) 1(-346.83,113.21) 1(-346.83,203.21) 1(-342.83,209.21) 1(-340.83,211.21) 1(-338.83,215.21) 1(-336.83,217.21) 1(-334.83,223.21) 1(-332.83,185.21) 1(-332.83,225.21) 1(-330.83,187.21) 1(-328.83,189.21) 1(-326.83,191.21) 1(-316.83,205.21) 1(-316.83,207.21) 1(-314.83,209.21) 1(-312.83,213.21) 1(-310.83,55.21) 1(-310.83,215.21) 1(-310.83,217.21) 1(-264.83,201.21) 1(-256.83,219.21) 1(-234.83,231.21) 1(-228.83,159.21) 1(-228.83,225.21) 1(-226.83,203.21) 1(-224.83,205.21) 1(-224.83,237.21) 1(-222.83,207.21) 1(-220.83,209.21) 1(-220.83,233.21) 1(-218.83,231.21) 1(-202.83,113.21) 1(-200.83,115.21) 1(-200.83,177.21) 1(-198.83,119.21) 1(-196.83,215.21) 1(-194.83,181.21) 1(-192.83,209.21) 1(-186.83,145.21) 1(-186.83,187.21) 1(-184.83,189.21) 1(-182.83,191.21) 1(-180.83,193.21) 1(-178.83,195.21) 1(-176.83,183.21) 1(-176.83,197.21) 1(-174.83,199.21) 1(-172.83,201.21) 1(-170.83,203.21) 1(-164.83,173.21) 1(-160.83,37.21) 1(-158.83,115.21) 1(-142.83,37.21)
  rect 10x2 on Top Overlay: 1(-439.83,53.21) 1(-437.83,55.21) 1(-435.83,57.21) 1(-435.83,179.21) 1(-433.83,59.21) 1(-433.83,181.21) 1(-431.83,61.21) 1(-429.83,63.21) 1(-429.83,183.21) 1(-427.83,65.21) 1(-425.83,185.21) 1(-423.83,71.21) 1(-423.83,187.21) 1(-421.83,73.21) 1(-419.83,189.21) 1(-417.83,191.21) 1(-415.83,193.21) 1(-413.83,195.21) 1(-411.83,197.21) 1(-405.83,203.21) 1(-403.83,205.21) 1(-401.83,113.21) 1(-401.83,207.21) 1(-399.83,211.21) 1(-397.83,197.21) 1(-397.83,213.21) 1(-395.83,217.21) 1(-391.83,193.21) 1(-389.83,191.21) 1(-387.83,189.21) 1(-385.83,185.21) 1(-385.83,187.21) 1(-377.83,13.21) 1(-371.83,157.21) 1(-349.83,173.21) 1(-345.83,175.21) 1(-343.83,111.21) 1(-343.83,177.21) 1(-341.83,109.21) 1(-339.83,107.21) 1(-339.83,179.21) 1(-337.83,181.21) 1(-335.83,183.21) 1(-333.83,231.21) 1(-331.83,227.21) 1(-331.83,229.21) 1(-313.83,211.21) 1(-309.83,57.21) 1(-309.83,219.21) 1(-279.83,93.21) 1(-277.83,95.21) 1(-275.83,11.21) 1(-275.83,211.21) 1(-267.83,205.21) 1(-265.83,203.21) 1(-265.83,227.21) 1(-263.83,175.21) 1(-259.83,223.21) 1(-257.83,221.21) 1(-249.83,65.21) 1(-241.83,191.21) 1(-239.83,193.21) 1(-235.83,195.21) 1(-233.83,197.21) 1(-231.83,199.21) 1(-231.83,229.21) 1(-229.83,201.21) 1(-229.83,227.21) 1(-209.83,73.21) 1(-207.83,83.21) 1(-207.83,85.21) 1(-207.83,87.21) 1(-207.83,89.21) 1(-207.83,91.21) 1(-207.83,93.21) 1(-207.83,95.21) 1(-199.83,117.21) 1(-197.83,121.21) 1(-197.83,179.21) 1(-195.83,123.21) 1(-191.83,183.21) 1(-189.83,185.21) 1(-175.83,61.21) 1(-173.83,181.21) 1(-165.83,233.21) 1(-161.83,229.21) 1(-159.83,39.21) 1(-141.83,31.21) 1(-141.83,33.21) 1(-141.83,35.21)
  rect 4x2 on Top Overlay: 1(-438.83,177.21) 1(-430.83,223.21) 1(-404.83,117.21) 1(-394.83,225.21) 1(-356.83,193.21) 1(-280.83,91.21) 1(-270.83,183.21) 1(-270.83,185.21) 1(-252.83,63.21) 1(-236.83,233.21) 1(-226.83,221.21) 1(-214.83,217.21) 1(-198.83,217.21) 1(-164.83,171.21) 1(-160.83,35.21)
  rect 12x2 on Top Overlay: 1(-426.83,67.21) 1(-424.83,69.21) 1(-420.83,75.21) 1(-418.83,77.21) 1(-416.83,79.21) 1(-416.83,81.21) 1(-414.83,83.21) 1(-412.83,87.21) 1(-410.83,89.21) 1(-408.83,93.21) 1(-394.83,195.21) 1(-392.83,219.21) 1(-370.83,31.21) 1(-370.83,33.21) 1(-370.83,35.21) 1(-370.83,37.21) 1(-370.83,39.21) 1(-370.83,41.21) 1(-370.83,43.21) 1(-370.83,45.21) 1(-370.83,47.21) 1(-370.83,49.21) 1(-370.83,51.21) 1(-370.83,53.21) 1(-370.83,55.21) 1(-370.83,57.21) 1(-370.83,59.21) 1(-370.83,61.21) 1(-370.83,63.21) 1(-370.83,65.21) 1(-370.83,67.21) 1(-370.83,69.21) 1(-370.83,71.21) 1(-370.83,73.21) 1(-370.83,75.21) 1(-370.83,77.21) 1(-370.83,79.21) 1(-370.83,81.21) 1(-370.83,83.21) 1(-370.83,85.21) 1(-370.83,87.21) 1(-370.83,89.21) 1(-370.83,91.21) 1(-370.83,93.21) 1(-370.83,95.21) 1(-370.83,97.21) 1(-370.83,99.21) 1(-370.83,101.21) 1(-370.83,103.21) 1(-370.83,105.21) 1(-370.83,107.21) 1(-370.83,109.21) 1(-370.83,111.21) 1(-370.83,113.21) 1(-370.83,115.21) 1(-370.83,117.21) 1(-370.83,119.21) 1(-370.83,121.21) 1(-370.83,123.21) 1(-370.83,125.21) 1(-370.83,127.21) 1(-370.83,129.21) 1(-370.83,131.21) 1(-370.83,133.21) 1(-370.83,135.21) 1(-370.83,137.21) 1(-370.83,139.21) 1(-370.83,141.21) 1(-370.83,143.21) 1(-370.83,145.21) 1(-370.83,147.21) 1(-338.83,105.21) 1(-336.83,103.21) 1(-334.83,101.21) 1(-320.83,197.21) 1(-320.83,199.21) 1(-310.83,59.21) 1(-274.83,97.21) 1(-272.83,99.21) 1(-268.83,207.21) 1(-264.83,105.21) 1(-252.83,117.21) 1(-252.83,183.21) 1(-250.83,185.21) 1(-248.83,67.21) 1(-248.83,69.21) 1(-248.83,71.21) 1(-248.83,73.21) 1(-248.83,79.21) 1(-248.83,81.21) 1(-248.83,83.21) 1(-248.83,85.21) 1(-248.83,87.21) 1(-248.83,89.21) 1(-248.83,91.21) 1(-248.83,93.21) 1(-248.83,95.21) 1(-248.83,97.21) 1(-248.83,99.21) 1(-248.83,101.21) 1(-248.83,103.21) 1(-248.83,105.21) 1(-246.83,187.21) 1(-244.83,189.21) 1(-222.83,235.21) 1(-218.83,47.21) 1(-216.83,51.21) 1(-214.83,55.21) 1(-214.83,57.21) 1(-212.83,59.21) 1(-212.83,61.21) 1(-212.83,63.21) 1(-210.83,65.21) 1(-210.83,67.21) 1(-210.83,69.21) 1(-210.83,71.21) 1(-208.83,79.21) 1(-208.83,81.21) 1(-206.83,97.21) 1(-206.83,99.21) 1(-206.83,101.21) 1(-206.83,103.21) 1(-206.83,105.21) 1(-194.83,31.21) 1(-194.83,33.21) 1(-194.83,35.21) 1(-194.83,37.21) 1(-194.83,39.21) 1(-194.83,41.21) 1(-194.83,43.21) 1(-194.83,45.21) 1(-194.83,47.21) 1(-194.83,49.21) 1(-194.83,51.21) 1(-194.83,53.21) 1(-194.83,55.21) 1(-194.83,57.21) 1(-194.83,59.21) 1(-194.83,61.21) 1(-194.83,63.21) 1(-194.83,65.21) 1(-194.83,67.21) 1(-194.83,69.21) 1(-194.83,71.21) 1(-194.83,73.21) 1(-194.83,125.21) 1(-192.83,127.21) 1(-186.83,143.21) 1(-164.83,175.21) 1(-164.83,209.21) 1(-164.83,211.21) 1(-160.83,41.21) 1(-160.83,43.21) 1(-158.83,69.21) 1(-158.83,71.21) 1(-158.83,73.21) 1(-158.83,79.21) 1(-158.83,81.21) 1(-158.83,83.21) 1(-158.83,85.21) 1(-158.83,87.21) 1(-158.83,89.21) 1(-158.83,91.21) 1(-158.83,93.21) 1(-158.83,95.21) 1(-158.83,97.21) 1(-158.83,99.21) 1(-158.83,101.21) 1(-158.83,103.21) 1(-158.83,105.21) 1(-158.83,113.21) 1(-140.83,217.21)
  rect 6x2 on Top Overlay: 1(-423.83,215.21) 1(-383.83,181.21) 1(-373.83,159.21) 1(-355.83,195.21) 1(-353.83,197.21) 1(-351.83,199.21) 1(-349.83,201.21) 1(-347.83,115.21) 1(-345.83,205.21) 1(-339.83,213.21) 1(-335.83,233.21) 1(-309.83,53.21) 1(-309.83,225.21) 1(-263.83,173.21) 1(-255.83,217.21) 1(-229.83,161.21) 1(-227.83,223.21) 1(-219.83,211.21) 1(-217.83,213.21) 1(-217.83,229.21) 1(-215.83,215.21) 1(-177.83,63.21) 1(-161.83,67.21) 1(-161.83,181.21) 1(-161.83,183.21) 1(-161.83,185.21) 1(-161.83,187.21) 1(-161.83,189.21) 1(-161.83,191.21) 1(-161.83,193.21) 1(-161.83,195.21) 1(-161.83,197.21) 1(-161.83,199.21) 1(-161.83,201.21) 1(-161.83,203.21) 1(-161.83,217.21) 1(-161.83,219.21) 1(-161.83,221.21) 1(-161.83,223.21) 1(-161.83,225.21) 1(-161.83,227.21) 1(-159.83,117.21) 1(-141.83,39.21) 1(-141.83,41.21) 1(-141.83,43.21) 1(-141.83,45.21) 1(-141.83,47.21) 1(-141.83,49.21) 1(-141.83,51.21) 1(-141.83,53.21) 1(-141.83,55.21)
  rect 16x2 on Top Overlay: 1(-422.83,217.21) 1(-406.83,97.21) 1(-404.83,101.21) 1(-402.83,103.21) 1(-396.83,223.21) 1(-394.83,29.21) 1(-376.83,17.21) 1(-368.83,151.21) 1(-332.83,219.21) 1(-328.83,95.21) 1(-326.83,93.21) 1(-324.83,91.21) 1(-322.83,89.21) 1(-322.83,193.21) 1(-322.83,201.21) 1(-320.83,85.21) 1(-320.83,195.21) 1(-310.83,63.21) 1(-310.83,65.21) 1(-310.83,67.21) 1(-262.83,177.21) 1(-238.83,27.21) 1(-234.83,29.21) 1(-234.83,143.21) 1(-232.83,31.21) 1(-232.83,145.21) 1(-230.83,33.21) 1(-230.83,147.21) 1(-226.83,155.21) 1(-192.83,27.21) 1(-190.83,25.21) 1(-186.83,141.21) 1(-168.83,55.21) 1(-166.83,53.21) 1(-166.83,179.21) 1(-166.83,205.21) 1(-164.83,51.21) 1(-162.83,47.21) 1(-162.83,49.21) 1(-140.83,27.21)
  rect 30x2 on Top Overlay: 1(-415.83,219.21) 1(-379.83,23.21)
  rect 14x2 on Top Overlay: 1(-413.83,85.21) 1(-409.83,91.21) 1(-407.83,95.21) 1(-405.83,99.21) 1(-405.83,201.21) 1(-401.83,111.21) 1(-377.83,15.21) 1(-371.83,29.21) 1(-369.83,149.21) 1(-369.83,155.21) 1(-331.83,99.21) 1(-331.83,205.21) 1(-329.83,97.21) 1(-309.83,61.21) 1(-273.83,209.21) 1(-269.83,101.21) 1(-267.83,103.21) 1(-263.83,225.21) 1(-253.83,115.21) 1(-251.83,119.21) 1(-249.83,121.21) 1(-247.83,123.21) 1(-245.83,125.21) 1(-245.83,127.21) 1(-243.83,129.21) 1(-241.83,131.21) 1(-241.83,133.21) 1(-239.83,135.21) 1(-235.83,141.21) 1(-227.83,35.21) 1(-227.83,157.21) 1(-225.83,37.21) 1(-223.83,39.21) 1(-223.83,41.21) 1(-221.83,43.21) 1(-219.83,45.21) 1(-217.83,49.21) 1(-215.83,53.21) 1(-193.83,29.21) 1(-191.83,129.21) 1(-189.83,131.21) 1(-173.83,59.21) 1(-171.83,57.21) 1(-165.83,177.21) 1(-165.83,207.21) 1(-163.83,231.21) 1(-161.83,45.21) 1(-141.83,29.21)
  rect 44x2 on Top Overlay: 1(-410.83,221.21)
  rect 20x2 on Top Overlay: 1(-404.83,199.21) 1(-400.83,105.21) 1(-400.83,107.21) 1(-338.83,207.21) 1(-324.83,203.21) 1(-266.83,15.21) 1(-262.83,179.21) 1(-260.83,17.21) 1(-254.83,19.21) 1(-226.83,153.21) 1(-184.83,135.21) 1(-140.83,25.21)
  rect 18x2 on Top Overlay: 1(-399.83,109.21) 1(-367.83,153.21) 1(-321.83,87.21) 1(-319.83,83.21) 1(-317.83,81.21) 1(-315.83,77.21) 1(-315.83,79.21) 1(-313.83,73.21) 1(-313.83,75.21) 1(-311.83,69.21) 1(-311.83,71.21) 1(-271.83,13.21) 1(-253.83,113.21) 1(-249.83,21.21) 1(-245.83,23.21) 1(-241.83,25.21) 1(-229.83,149.21) 1(-227.83,151.21) 1(-187.83,133.21)
  rect 38x2 on Top Overlay: 1(-383.83,27.21)
  rect 36x2 on Top Overlay: 1(-382.83,25.21) 1(-320.83,221.21)
  rect 24x2 on Top Overlay: 1(-378.83,21.21) 1(-314.83,223.21) 1(-260.83,181.21) 1(-186.83,211.21)
  rect 22x2 on Top Overlay: 1(-377.83,19.21)
  rect 2x2 on Top Overlay: 1(-353.83,169.21) 1(-347.83,117.21) 1(-217.83,227.21) 1(-201.83,175.21) 1(-187.83,147.21) 1(-177.83,185.21)
  rect 68x2 on Top Overlay: 1(-210.83,139.21) 1(-164.83,23.21)
  rect 118x2 on Top Overlay: 1(-209.83,107.21) 1(-207.83,109.21)
  rect 70x2 on Top Overlay: 1(-209.83,137.21) 1(-165.83,213.21)
  rect 116x2 on Top Overlay: 1(-206.83,111.21)
  rect 102x2 on Top Overlay: 1(-203.83,75.21) 1(-203.83,77.21)
  rect 54x2 on Top Overlay: 1(-165.83,15.21)
  rect 58x2 on Top Overlay: 1(-165.83,17.21)
  rect 66x2 on Top Overlay: 1(-165.83,21.21)
  rect 64x2 on Top Overlay: 1(-164.83,19.21)
  rect 50x2 on Top Overlay: 1(-157.83,215.21)

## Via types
v1: diameter 19.68, hole 9.84, Top Layer to Bottom Layer, tented top, 176 vias
v2: diameter 25.98, hole 12.99, Top Layer to Bottom Layer, tented top, 36 vias
v3: diameter 20, hole 10, Top Layer to Bottom Layer, tented bottom, 2 vias

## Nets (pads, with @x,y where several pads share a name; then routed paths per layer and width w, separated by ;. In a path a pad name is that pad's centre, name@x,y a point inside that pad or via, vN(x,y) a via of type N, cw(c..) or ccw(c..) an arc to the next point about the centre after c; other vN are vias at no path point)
AUX_I2C_SCL: JP10C.48 U10C.14 | length 742.3
  Top Layer w5: U10C.14@-561.25,-325 -527.99,-358.27 v1(-474.41,-358.27)
  Bottom Layer w5: v1(-474.41,-358.27) -474.41,-246.06 -456.69,-228.35 -410.43,-228.35 -303.15,-121.06 -303.15,0 -351.38,48.23 -383.86,48.23 -429.13,93.5 JP10C.48@-429.13,114.17
AUX_I2C_SDA: JP10C.47 U10C.15 | length 550.4
  Top Layer w5: U10C.15@-547.33,-311.09 v1(-519.83,-338.58)
  Bottom Layer w5: v1(-519.83,-338.58) -486.22,-304.97 -486.22,-242.13 -445.87,-201.77 -445.87,-116.14 -431.1,-101.38 -431.1,-30.51 -445.87,-15.75 -445.87,26.57 -428.15,44.29 -428.15,75.79 -448.82,96.46 JP10C.47@-448.82,114.17
BATT_VDD: C23C.1 C34C.1 C35C.1 JP10C.1 JP10C.2 JP10C.3 JP10C.4 JP10C.5 P10C.26 P10C.27 P10C.28 P10C.29 | length 2095
  Top Layer w10: P10C.29@-1531.5,-848.43 -1497.05,-848.43 -1483.27,-834.65 v1@-1483.27,-828.74 ; P10C.28@-1531.5,-828.74 v1@-1483.27,-828.74 ; P10C.27@-1531.5,-809.06 -1483.27,-809.06 ; P10C.26@-1531.5,-789.37 -1496.06,-789.37 -1483.27,-802.17 -1483.27,-809.06 v1@-1483.27,-828.74 ; v1(-1294.29,71.85) C35C.1@-1294.29,113.19
  Top Layer w20: C23C.1@-1375.98,-852.36 -1319.88,-852.36 C34C.1@-1288.39,-820.87
  Top Layer w40: -1475.39,-814.96 -1475.39,-817.91 -1440.94,-852.36 C23C.1@-1375.98,-852.36
  Bottom Layer w10: JP10C.1@-1354.33,114.17 -1354.33,86.61 -1340.55,72.83 -1332.68,72.83 ; JP10C.2@-1334.65,114.17 -1334.65,74.8 -1332.68,72.83 ; JP10C.3@-1314.96,114.17 -1314.96,73.33 -1314.47,72.83 ; JP10C.4@-1295.28,114.17 -1295.28,79.72 v1@-1288.39,72.83 ; JP10C.5@-1275.59,114.17 -1275.59,85.63 v1@-1288.39,72.83 ; -1332.68,72.83 -1314.47,72.83 ; -1314.47,72.83 v1@-1288.39,72.83
  Bottom Layer w50: v1(-1448.82,-833.66) -1453.74,-833.66 -1473.43,-813.98 -1586.61,-813.98 -1651.57,-749.02 -1651.57,-227.36 -1564.96,-140.75 -1342.52,-140.75 -1289.37,-87.6 -1289.37,59.06
  other v1: -1479.33,-830.71 -1472.44,-804.13
C_EDP_TX0_N: C12C.1 P10C.6 | length 101.6
  Top Layer w4.02: P10C.6@-1531.5,-395.67 -1515.59,-395.67 -1511.81,-399.45 -1491.97,-399.45 -1491.14,-398.62 -1442.91,-398.62 C12C.1@-1435.04,-390.75
C_EDP_TX0_P: C13C.1 P10C.7 | length 104.2
  Top Layer w4.02: P10C.7@-1531.5,-415.35 -1517.72,-415.35 -1510.83,-408.46 -1488.23,-408.46 -1487.41,-407.64 -1442.76,-407.64 C13C.1@-1434.06,-416.34
C_EDP_TX1_N: C10C.1 P10C.3 | length 113
  Top Layer w4.02: P10C.3@-1531.5,-336.61 -1515.59,-336.61 -1511.81,-340.39 -1500.78,-340.39 -1472.24,-311.85 -1442.76,-311.85 C10C.1@-1435.04,-304.13
C_EDP_TX1_P: C11C.1 P10C.4 | length 114.4
  Top Layer w4.02: P10C.4@-1531.5,-356.3 -1517.72,-356.3 -1510.83,-349.41 -1497.05,-349.41 -1468.5,-320.87 -1442.91,-320.87 C11C.1@-1435.04,-328.74
C_EDP_TXAUX_N: C15C.1 P10C.10 R30C.1 | length 204.4
  Top Layer w4.02: P10C.10@-1531.5,-474.41 -1517.72,-474.41 -1510.83,-467.52 -1491.14,-467.52 -1464.57,-494.09 -1442.91,-494.09 C15C.1@-1435.04,-501.97
  Bottom Layer w4.02: R30C.1@-1527.56,-476.38 -1523.62,-476.38 -1511.81,-464.57 -1493.11,-464.57 v1(-1456.69,-500.98)
C_EDP_TXAUX_P: C14C.1 P10C.9 R31C.1 | length 201
  Top Layer w4.02: P10C.9@-1531.5,-454.72 -1515.59,-454.72 -1511.81,-458.5 -1487.41,-458.5 v1@-1463.11,-482.8 ; v1@-1460.83,-485.08 -1442.76,-485.08 C14C.1@-1435.04,-477.36
  Bottom Layer w4.02: R31C.1@-1527.56,-429.13 -1501.14,-455.55 -1489.33,-455.55 -1466.56,-478.32 -1458.64,-478.32 v1(-1456.69,-476.38)
DBG0: J15C.1 U10C.8 | length 741.5
  Top Layer w4: U10C.8@-644.77,-408.52 -618.25,-435.04 -611.22,-435.04 -566.93,-479.33 -566.93,-537.4 -577.76,-548.23 -577.76,-607.28 v1(-566.93,-618.11)
  Bottom Layer w4: v1(-1007.87,-728.35) -964.57,-685.04 -818.9,-685.04 -788.39,-654.53 -603.35,-654.53 v1(-566.93,-618.11)
DBG1: J13C.1 U10C.9 | length 803.7
  Top Layer w4: U10C.9@-630.85,-394.6 -619.09,-406.36 -619.09,-415.35 -558.93,-475.52 -558.93,-495.2 v1(-544.29,-509.84)
  Bottom Layer w4: v1(-944.88,-728.35) -917.32,-755.91 -807.09,-755.91 -738.19,-687.01 -540.35,-687.01 -504.92,-651.57 -504.92,-591.54 -544.29,-552.17 v1(-544.29,-509.84)
DBG2: J12C.1 U10C.10 | length 692.6
  Top Layer w6: U10C.10@-616.93,-380.68 -597.44,-400.17 v1(-597.44,-413.39)
  Bottom Layer w6: v1(-881.89,-728.35) -807.09,-728.35 -748.03,-669.29 -562.99,-669.29 -516.73,-623.03 -516.73,-594.49 -572.83,-538.39 -572.83,-465.55 -597.44,-440.94 v1(-597.44,-413.39)
EDP_HPD: P10C.17 R24C.2 R25C.1 R29C.2 | length 283.3
  Top Layer w6: P10C.17@-1531.5,-612.2 -1478.35,-612.2 v1@-1435.04,-655.51 ; v1(-1434.06,-655.51) R24C.2@-1375.98,-655.51 -1377.95,-653.54 R25C.1@-1377.95,-606.3
  Bottom Layer w6: v1(-1434.06,-655.51) -1375.98,-655.51 R29C.2@-1374.02,-657.48
EDP_TX0_N: C12C.2 U10C.59 | length 649.6
  Top Layer w4.02: C12C.2@-1374.02,-381.89 -1371.06,-381.89 -1353.5,-399.45 -1237.36,-399.45 -1083.66,-553.15 -988.14,-553.15 -939.45,-504.45 -939.45,-494.56 -934.06,-489.17 -924.17,-489.17 -915.15,-480.16 -905.35,-480.16 -890.59,-465.39 -874.66,-465.39 -863.1,-453.83 -863.1,-444.51 U10C.59@-854.95,-436.36
EDP_TX0_P: C13C.2 U10C.60 | length 649.9
  Top Layer w4.02: C13C.2@-1374.02,-425.2 -1370.08,-425.2 -1353.35,-408.46 -1241.1,-408.46 -1087.4,-562.17 -984.41,-562.17 -911.42,-489.17 -901.62,-489.17 -886.86,-474.41 -870.93,-474.41 -854.76,-458.24 -848.99,-458.24 U10C.60@-841.03,-450.28
EDP_TX1_N: C10C.2 U10C.56 | length 628.4
  Top Layer w4.02: C10C.2@-1374.02,-295.28 -1368.11,-295.28 -1351.38,-312.01 -1247.05,-312.01 -1050.2,-508.86 -994.09,-508.86 -928.15,-442.91 -928.15,-435.36 -924.54,-431.76 -924.54,-422.57 -919.45,-417.49 -910.27,-417.49 -904.86,-412.07 -904.86,-402.75 U10C.56@-896.71,-394.6
EDP_TX1_P: C11C.2 U10C.57 | length 629.8
  Top Layer w4.02: C11C.2@-1374.02,-338.58 -1369.09,-338.58 -1351.54,-321.02 -1250.78,-321.02 -1053.93,-517.87 -990.36,-517.87 -919.13,-446.65 -919.13,-439.1 -896.51,-416.48 -890.75,-416.48 U10C.57@-882.79,-408.52
EDP_TXAUX_N: C15C.2 U10C.47 | length 724.6
  Top Layer w4.02: C15C.2@-1374.02,-511.81 -1370.08,-511.81 -1353.35,-495.08 v1@-1329.72,-495.08 ; v1@-1184.06,-243.11 -1062.99,-243.11 -1044.29,-224.41 -1005.24,-224.41 -997.7,-231.95 -988.37,-231.95 U10C.47@-980.23,-240.1
  Bottom Layer w4.02: v1@-1327.76,-495.24 -1361.02,-495.24 -1379.09,-477.16 -1379.09,-292.53 -1329.52,-242.95 v1@-1187.79,-242.95
  other v1: -1328.74,-502.95 -1184.06,-235.24
EDP_TXAUX_P: C14C.2 U10C.48 | length 722.5
  Top Layer w4.02: C14C.2@-1374.02,-468.5 -1371.06,-468.5 -1353.5,-486.06 v1@-1329.72,-486.06 ; v1@-1184.06,-252.13 -1146.65,-252.13 -1137.95,-260.83 -1125.83,-260.83 -1117.13,-252.13 -1098.43,-252.13 -1089.72,-260.83 -1078.58,-260.83 -1069.88,-252.13 -1059.26,-252.13 -1040.56,-233.43 -1008.97,-233.43 -1002.1,-240.29 -1002.1,-246.06 U10C.48@-994.15,-254.02
  Bottom Layer w4.02: v1@-1327.76,-486.22 -1357.28,-486.22 -1370.08,-473.43 -1370.08,-468.5 -1364.17,-462.6 -1364.17,-454.72 -1370.08,-448.82 -1370.08,-296.26 -1365.16,-291.34 -1354.33,-291.34 -1347.93,-284.94 -1347.93,-274.11 -1325.79,-251.97 -1309.06,-251.97 -1301.18,-259.84 -1289.37,-259.84 -1281.5,-251.97 v1@-1184.06,-251.97
  other v1: -1328.74,-478.35 -1184.06,-259.84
